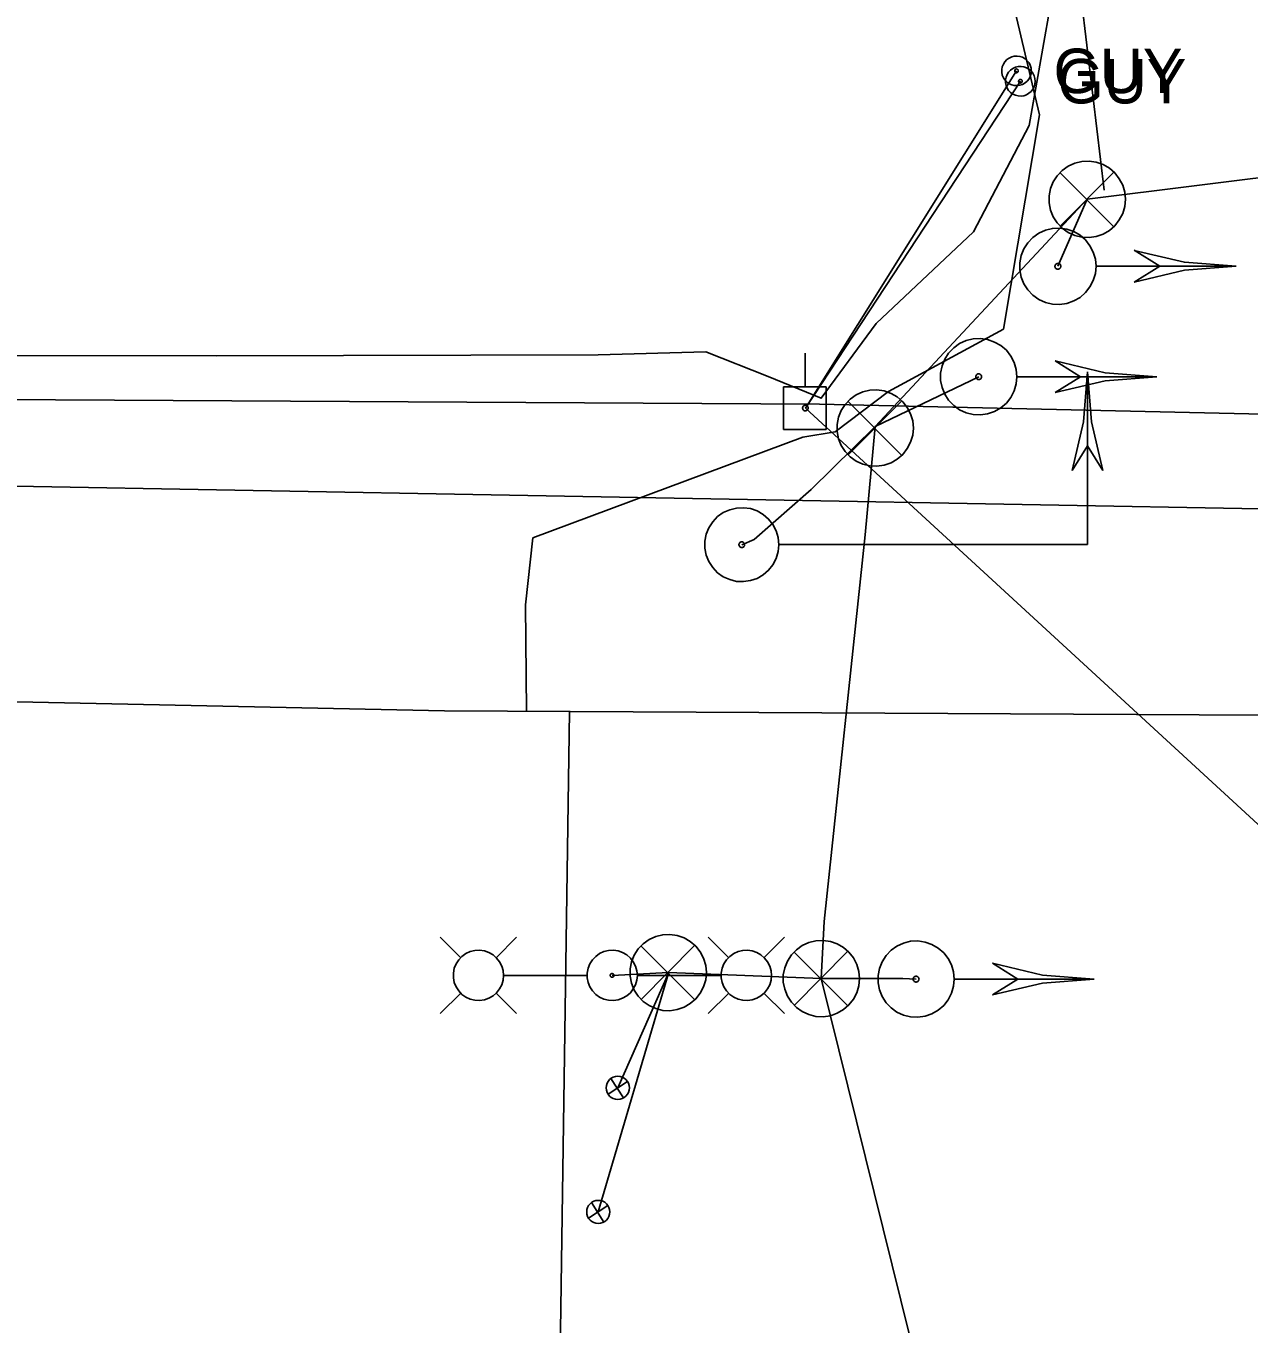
# Model space of a CAD drawing. Extents: x 596028 to 606371, y 330010 to 403088.
# Drawn here: x 604901.1 to 605006.9, y 349899.9 to 350012.1 of the extents above; entities that cross this region are included whole.
import ezdxf

# ---------------------------------------------------------------- set-up
doc = ezdxf.new("R2010")
doc.units = 0
for name, color, linetype in [('E_LTG', 7, 'Continuous'), ('E_LTG_CID', 7, 'Continuous'), ('E_SIG', 7, 'Continuous'), ('E_SIG_Conduit', 7, 'Continuous'), ('E_UTL_EGuyWire', 7, 'Continuous'), ('E_UTL_EPowerPole', 7, 'Continuous'), ('E_UTL_G_UG', 7, 'Continuous'), ('E_UTL_Loop_UG', 7, 'Continuous'), ('E_UTL_Overhead', 7, 'Continuous'), ('E_UTL_SAN_UG', 7, 'Continuous'), ('E_UTL_TV_UG', 7, 'Continuous')]:
    doc.layers.add(name, color=color, linetype=linetype)

# ---------------------------------------------------------------- blocks, each defined once
blk = doc.blocks.new('_U360')
at = {"layer": 'E_SIG'}
for p, q in [((-6.09, 0.4), (6.1, 0.4)), ((0, 6.1), (0, -6.1))]:
    blk.add_line(p, q, dxfattribs=at)
blk.add_circle((0, 0.01), 6.1, dxfattribs=at)
blk = doc.blocks.new('_U361')
at = {"layer": 'E_SIG'}
for p, q in [((-6.09, 0.4), (6.1, 0.4)), ((0, 6.1), (0, -6.1))]:
    blk.add_line(p, q, dxfattribs=at)
blk.add_circle((0, 0.01), 6.1, dxfattribs=at)

msp = doc.modelspace()

# ---------------------------------------------------------------- linework, layer by layer
at = {"layer": 'E_LTG'}
for points in [[(604938.74, 349931.53), (604936.97, 349933.3)], [(604941.79, 349931.53), (604943.57, 349933.3)], [(604961.92, 349931.53), (604960.14, 349933.3)], [(604964.96, 349931.53), (604966.74, 349933.3)], [(604942.44, 349930), (604942.4, 349930.42), (604942.29, 349930.81), (604942.1, 349931.18), (604941.84, 349931.5), (604941.53, 349931.78), (604941.17, 349931.98), (604940.78, 349932.12), (604940.37, 349932.18), (604939.96, 349932.16), (604939.56, 349932.06), (604939.18, 349931.89), (604938.84, 349931.65), (604938.56, 349931.35), (604938.33, 349931), (604938.18, 349930.62), (604938.1, 349930.21), (604938.1, 349929.8), (604938.18, 349929.39), (604938.33, 349929.01), (604938.56, 349928.66), (604938.84, 349928.36), (604939.18, 349928.12), (604939.56, 349927.95), (604939.96, 349927.85), (604940.37, 349927.83), (604940.78, 349927.89), (604941.17, 349928.02), (604941.53, 349928.23), (604941.84, 349928.5), (604942.1, 349928.83), (604942.29, 349929.19), (604942.4, 349929.59), (604942.44, 349930)], [(604954.01, 349930), (604953.97, 349930.41), (604953.85, 349930.81), (604953.66, 349931.18), (604953.41, 349931.5), (604953.1, 349931.78), (604952.74, 349931.98), (604952.35, 349932.12), (604951.94, 349932.18), (604951.52, 349932.16), (604951.12, 349932.06), (604950.75, 349931.89), (604950.41, 349931.65), (604950.12, 349931.35), (604949.9, 349931), (604949.75, 349930.62), (604949.67, 349930.21), (604949.67, 349929.8), (604949.75, 349929.39), (604949.9, 349929.01), (604950.12, 349928.66), (604950.41, 349928.36), (604950.75, 349928.12), (604951.12, 349927.95), (604951.52, 349927.85), (604951.94, 349927.83), (604952.35, 349927.89), (604952.74, 349928.02), (604953.1, 349928.23), (604953.41, 349928.5), (604953.66, 349928.83), (604953.85, 349929.19), (604953.97, 349929.59), (604954.01, 349930)], [(604965.61, 349930), (604965.57, 349930.41), (604965.46, 349930.81), (604965.27, 349931.18), (604965.01, 349931.5), (604964.7, 349931.78), (604964.34, 349931.98), (604963.95, 349932.12), (604963.54, 349932.18), (604963.13, 349932.16), (604962.73, 349932.06), (604962.35, 349931.89), (604962.01, 349931.65), (604961.73, 349931.35), (604961.5, 349931), (604961.35, 349930.62), (604961.27, 349930.21), (604961.27, 349929.8), (604961.35, 349929.39), (604961.5, 349929.01), (604961.73, 349928.66), (604962.01, 349928.36), (604962.35, 349928.12), (604962.73, 349927.95), (604963.13, 349927.85), (604963.54, 349927.83), (604963.95, 349927.89), (604964.34, 349928.02), (604964.7, 349928.23), (604965.01, 349928.5), (604965.27, 349928.83), (604965.46, 349929.19), (604965.57, 349929.59), (604965.61, 349930)], [(604942.48, 349930), (604949.66, 349930)], [(604952, 349930), (604952, 349930.03), (604951.99, 349930.06), (604951.97, 349930.09), (604951.95, 349930.12), (604951.93, 349930.14), (604951.9, 349930.15), (604951.87, 349930.16), (604951.84, 349930.17), (604951.81, 349930.17), (604951.78, 349930.16), (604951.75, 349930.15), (604951.73, 349930.13), (604951.7, 349930.11), (604951.69, 349930.08), (604951.67, 349930.05), (604951.67, 349930.02), (604951.67, 349929.99), (604951.67, 349929.96), (604951.69, 349929.93), (604951.7, 349929.9), (604951.73, 349929.88), (604951.75, 349929.86), (604951.78, 349929.85), (604951.81, 349929.84), (604951.84, 349929.84), (604951.87, 349929.84), (604951.9, 349929.85), (604951.93, 349929.87), (604951.95, 349929.89), (604951.97, 349929.91), (604951.99, 349929.94), (604952, 349929.97), (604952, 349930)], [(604961.22, 349930), (604954.05, 349930)], [(604938.74, 349928.48), (604936.97, 349926.7)], [(604941.79, 349928.48), (604943.57, 349926.7)], [(604961.92, 349928.48), (604960.14, 349926.7)], [(604964.96, 349928.48), (604966.74, 349926.7)]]:
    msp.add_lwpolyline(points, dxfattribs=at)
at = {"layer": 'E_LTG_CID'}
msp.add_lwpolyline([(604956.7, 349930.25), (604951.83, 349930)], dxfattribs=at)
at = {"layer": 'E_SIG'}
for points in [[(604996.22, 349997.12), (604996.16, 349997.74), (604995.98, 349998.35), (604995.69, 349998.9), (604995.31, 349999.4), (604994.83, 349999.81), (604994.29, 350000.12), (604993.7, 350000.33), (604993.08, 350000.42), (604992.45, 350000.39), (604991.84, 350000.24), (604991.27, 349999.98), (604990.76, 349999.61), (604990.32, 349999.16), (604989.98, 349998.63), (604989.75, 349998.05), (604989.63, 349997.43), (604989.63, 349996.81), (604989.75, 349996.19), (604989.98, 349995.61), (604990.32, 349995.08), (604990.76, 349994.63), (604991.27, 349994.26), (604991.84, 349994), (604992.45, 349993.85), (604993.08, 349993.82), (604993.7, 349993.91), (604994.29, 349994.12), (604994.83, 349994.43), (604995.31, 349994.84), (604995.69, 349995.34), (604995.98, 349995.89), (604996.16, 349996.5), (604996.22, 349997.12)], [(604995.18, 349999.45), (604990.57, 349994.8)], [(604990.57, 349999.41), (604995.22, 349994.75)], [(604993.68, 349991.33), (604993.62, 349991.95), (604993.44, 349992.56), (604993.15, 349993.11), (604992.76, 349993.61), (604992.29, 349994.02), (604991.75, 349994.33), (604991.15, 349994.54), (604990.53, 349994.63), (604989.91, 349994.6), (604989.3, 349994.45), (604988.73, 349994.19), (604988.21, 349993.82), (604987.78, 349993.37), (604987.44, 349992.84), (604987.21, 349992.26), (604987.09, 349991.64), (604987.09, 349991.02), (604987.21, 349990.4), (604987.44, 349989.82), (604987.78, 349989.29), (604988.21, 349988.84), (604988.73, 349988.47), (604989.3, 349988.21), (604989.91, 349988.06), (604990.53, 349988.03), (604991.15, 349988.12), (604991.75, 349988.33), (604992.29, 349988.64), (604992.76, 349989.05), (604993.15, 349989.55), (604993.44, 349990.1), (604993.62, 349990.7), (604993.68, 349991.33)], [(604999.18, 349991.33), (604996.98, 349992.71)], [(605005.78, 349991.33), (605001.32, 349991.68), (604996.98, 349992.7)], [(604990.63, 349991.33), (604990.62, 349991.38), (604990.61, 349991.42), (604990.59, 349991.47), (604990.56, 349991.5), (604990.52, 349991.54), (604990.48, 349991.56), (604990.44, 349991.57), (604990.39, 349991.58), (604990.34, 349991.58), (604990.29, 349991.57), (604990.25, 349991.55), (604990.21, 349991.52), (604990.18, 349991.49), (604990.15, 349991.45), (604990.13, 349991.4), (604990.12, 349991.35), (604990.12, 349991.31), (604990.13, 349991.26), (604990.15, 349991.21), (604990.18, 349991.17), (604990.21, 349991.14), (604990.25, 349991.11), (604990.29, 349991.09), (604990.34, 349991.08), (604990.39, 349991.08), (604990.44, 349991.08), (604990.48, 349991.1), (604990.52, 349991.12), (604990.56, 349991.16), (604990.59, 349991.19), (604990.61, 349991.24), (604990.62, 349991.28), (604990.63, 349991.33)], [(605005.78, 349991.33), (604993.73, 349991.33)], [(605005.78, 349991.33), (605001.32, 349990.98), (604996.98, 349989.95)], [(604996.98, 349989.96), (604999.18, 349991.33)], [(604986.83, 349981.78), (604986.77, 349982.4), (604986.59, 349983.01), (604986.3, 349983.56), (604985.92, 349984.06), (604985.44, 349984.47), (604984.9, 349984.78), (604984.3, 349984.99), (604983.68, 349985.07), (604983.06, 349985.04), (604982.45, 349984.9), (604981.88, 349984.64), (604981.37, 349984.27), (604980.93, 349983.82), (604980.59, 349983.29), (604980.36, 349982.71), (604980.24, 349982.09), (604980.24, 349981.46), (604980.36, 349980.85), (604980.59, 349980.27), (604980.93, 349979.74), (604981.37, 349979.28), (604981.88, 349978.92), (604982.45, 349978.66), (604983.06, 349978.51), (604983.68, 349978.48), (604984.3, 349978.57), (604984.9, 349978.78), (604985.44, 349979.09), (604985.92, 349979.5), (604986.3, 349979.99), (604986.59, 349980.55), (604986.77, 349981.15), (604986.83, 349981.78)], [(604998.93, 349981.78), (604994.47, 349982.12), (604990.13, 349983.15)], [(604992.33, 349981.78), (604990.13, 349983.15)], [(604983.78, 349981.78), (604983.77, 349981.83), (604983.76, 349981.87), (604983.74, 349981.91), (604983.71, 349981.95), (604983.67, 349981.98), (604983.63, 349982.01), (604983.59, 349982.02), (604983.54, 349982.03), (604983.49, 349982.03), (604983.44, 349982.02), (604983.4, 349982), (604983.36, 349981.97), (604983.33, 349981.93), (604983.3, 349981.89), (604983.28, 349981.85), (604983.28, 349981.8), (604983.28, 349981.75), (604983.28, 349981.71), (604983.3, 349981.66), (604983.33, 349981.62), (604983.36, 349981.59), (604983.4, 349981.56), (604983.44, 349981.54), (604983.49, 349981.53), (604983.54, 349981.53), (604983.59, 349981.53), (604983.63, 349981.55), (604983.67, 349981.57), (604983.71, 349981.6), (604983.74, 349981.64), (604983.76, 349981.68), (604983.77, 349981.73), (604983.78, 349981.78)], [(604998.93, 349981.78), (604986.88, 349981.78)], [(604998.93, 349981.78), (604994.47, 349981.43), (604990.13, 349980.4)], [(604990.13, 349980.41), (604992.33, 349981.78)], [(604992.94, 349982.2), (604992.6, 349977.88), (604991.6, 349973.66)], [(604992.94, 349967.26), (604992.94, 349982.2)], [(604992.94, 349982.2), (604993.27, 349977.88), (604994.27, 349973.66)], [(604977.88, 349977.34), (604977.82, 349977.96), (604977.64, 349978.57), (604977.35, 349979.12), (604976.96, 349979.62), (604976.49, 349980.03), (604975.95, 349980.34), (604975.35, 349980.55), (604974.73, 349980.64), (604974.11, 349980.61), (604973.5, 349980.46), (604972.93, 349980.2), (604972.42, 349979.83), (604971.98, 349979.38), (604971.64, 349978.85), (604971.41, 349978.27), (604971.29, 349977.65), (604971.29, 349977.03), (604971.41, 349976.41), (604971.64, 349975.83), (604971.98, 349975.3), (604972.42, 349974.85), (604972.93, 349974.48), (604973.5, 349974.22), (604974.11, 349974.07), (604974.73, 349974.04), (604975.35, 349974.13), (604975.95, 349974.34), (604976.49, 349974.65), (604976.96, 349975.06), (604977.35, 349975.56), (604977.64, 349976.11), (604977.82, 349976.72), (604977.88, 349977.34)], [(604976.84, 349979.67), (604972.23, 349975.02)], [(604972.23, 349979.63), (604976.88, 349974.97)], [(604992.94, 349975.8), (604991.6, 349973.66)], [(604994.27, 349973.66), (604992.94, 349975.8)], [(604966.25, 349967.25), (604966.19, 349967.86), (604966.02, 349968.44), (604965.74, 349968.99), (604965.36, 349969.46), (604964.9, 349969.86), (604964.37, 349970.17), (604963.8, 349970.37), (604963.2, 349970.45), (604962.59, 349970.42), (604962, 349970.28), (604961.44, 349970.03), (604960.95, 349969.68), (604960.53, 349969.23), (604960.2, 349968.72), (604959.97, 349968.16), (604959.86, 349967.56), (604959.86, 349966.95), (604959.97, 349966.35), (604960.2, 349965.79), (604960.53, 349965.27), (604960.95, 349964.83), (604961.44, 349964.48), (604962, 349964.23), (604962.59, 349964.08), (604963.2, 349964.06), (604963.8, 349964.14), (604964.37, 349964.34), (604964.9, 349964.65), (604965.36, 349965.04), (604965.74, 349965.52), (604966.02, 349966.06), (604966.19, 349966.65), (604966.25, 349967.25)], [(604963.29, 349967.25), (604963.28, 349967.3), (604963.27, 349967.35), (604963.25, 349967.39), (604963.22, 349967.42), (604963.19, 349967.45), (604963.15, 349967.48), (604963.1, 349967.49), (604963.06, 349967.5), (604963.01, 349967.5), (604962.96, 349967.49), (604962.92, 349967.47), (604962.88, 349967.44), (604962.85, 349967.41), (604962.83, 349967.37), (604962.81, 349967.32), (604962.8, 349967.28), (604962.8, 349967.23), (604962.81, 349967.19), (604962.83, 349967.14), (604962.85, 349967.1), (604962.88, 349967.07), (604962.92, 349967.04), (604962.96, 349967.02), (604963.01, 349967.01), (604963.06, 349967.01), (604963.1, 349967.02), (604963.15, 349967.03), (604963.19, 349967.05), (604963.22, 349967.09), (604963.25, 349967.12), (604963.27, 349967.16), (604963.28, 349967.21), (604963.29, 349967.25)], [(604992.94, 349967.26), (604966.3, 349967.26)], [(604985.46, 349967.26), (604985.46, 349967.26)], [(604959.98, 349930.25), (604959.92, 349930.87), (604959.74, 349931.48), (604959.45, 349932.03), (604959.07, 349932.53), (604958.59, 349932.94), (604958.05, 349933.25), (604957.46, 349933.46), (604956.83, 349933.55), (604956.21, 349933.52), (604955.6, 349933.37), (604955.03, 349933.11), (604954.52, 349932.74), (604954.08, 349932.29), (604953.74, 349931.76), (604953.51, 349931.18), (604953.39, 349930.56), (604953.39, 349929.94), (604953.51, 349929.32), (604953.74, 349928.74), (604954.08, 349928.21), (604954.52, 349927.75), (604955.03, 349927.39), (604955.6, 349927.13), (604956.21, 349926.98), (604956.83, 349926.95), (604957.46, 349927.04), (604958.05, 349927.25), (604958.59, 349927.56), (604959.07, 349927.97), (604959.45, 349928.46), (604959.74, 349929.02), (604959.92, 349929.62), (604959.98, 349930.25)], [(604958.94, 349932.58), (604954.33, 349927.93)], [(604954.33, 349932.54), (604958.98, 349927.88)], [(604973.22, 349929.73), (604973.16, 349930.35), (604972.98, 349930.95), (604972.7, 349931.51), (604972.31, 349932.01), (604971.83, 349932.42), (604971.29, 349932.73), (604970.7, 349932.94), (604970.08, 349933.02), (604969.45, 349932.99), (604968.84, 349932.85), (604968.27, 349932.59), (604967.76, 349932.22), (604967.33, 349931.77), (604966.99, 349931.24), (604966.75, 349930.66), (604966.63, 349930.04), (604966.63, 349929.41), (604966.75, 349928.8), (604966.99, 349928.22), (604967.33, 349927.69), (604967.76, 349927.23), (604968.27, 349926.87), (604968.84, 349926.61), (604969.45, 349926.46), (604970.08, 349926.43), (604970.7, 349926.52), (604971.29, 349926.73), (604971.83, 349927.04), (604972.31, 349927.45), (604972.7, 349927.94), (604972.98, 349928.5), (604973.16, 349929.1), (604973.22, 349929.73)], [(604981.41, 349929.68), (604981.35, 349930.31), (604981.18, 349930.91), (604980.89, 349931.47), (604980.5, 349931.96), (604980.03, 349932.37), (604979.48, 349932.68), (604978.89, 349932.89), (604978.27, 349932.98), (604977.64, 349932.95), (604977.03, 349932.8), (604976.46, 349932.54), (604975.95, 349932.18), (604975.52, 349931.72), (604975.18, 349931.19), (604974.95, 349930.61), (604974.83, 349930), (604974.83, 349929.37), (604974.95, 349928.75), (604975.18, 349928.17), (604975.52, 349927.64), (604975.95, 349927.19), (604976.46, 349926.82), (604977.03, 349926.56), (604977.64, 349926.42), (604978.27, 349926.39), (604978.89, 349926.48), (604979.48, 349926.68), (604980.03, 349926.99), (604980.5, 349927.41), (604980.89, 349927.9), (604981.18, 349928.46), (604981.35, 349929.06), (604981.41, 349929.68)], [(604972.18, 349932.06), (604967.57, 349927.41)], [(604967.57, 349932.02), (604972.22, 349927.36)], [(604993.51, 349929.68), (604989.06, 349930.03), (604984.71, 349931.06)], [(604986.91, 349929.68), (604984.71, 349931.06)], [(604978.37, 349929.68), (604978.36, 349929.73), (604978.35, 349929.78), (604978.33, 349929.82), (604978.3, 349929.86), (604978.26, 349929.89), (604978.22, 349929.91), (604978.17, 349929.93), (604978.13, 349929.93), (604978.08, 349929.93), (604978.03, 349929.92), (604977.99, 349929.9), (604977.95, 349929.87), (604977.92, 349929.84), (604977.89, 349929.8), (604977.87, 349929.75), (604977.86, 349929.71), (604977.86, 349929.66), (604977.87, 349929.61), (604977.89, 349929.57), (604977.92, 349929.53), (604977.95, 349929.49), (604977.99, 349929.46), (604978.03, 349929.44), (604978.08, 349929.43), (604978.13, 349929.43), (604978.17, 349929.44), (604978.22, 349929.45), (604978.26, 349929.48), (604978.3, 349929.51), (604978.33, 349929.55), (604978.35, 349929.59), (604978.36, 349929.63), (604978.37, 349929.68)], [(604993.51, 349929.68), (604981.47, 349929.68)], [(604993.51, 349929.68), (604989.06, 349929.34), (604984.71, 349928.31)], [(604984.71, 349928.31), (604986.91, 349929.68)]]:
    msp.add_lwpolyline(points, dxfattribs=at)
at = {"layer": 'E_SIG_Conduit'}
for points in [[(604994.39, 349997.92), (604992.49, 350013.82), (604988.54, 350029.6)], [(604992.92, 349997.12), (605041.26, 350003.17), (605045.68, 350004), (605067.59, 350003.14), (605103.15, 349993.06), (605106.99, 349992.73)], [(604963.04, 349967.25), (604964.1, 349967.7), (604969.04, 349972.01), (604974.59, 349977.47), (604992.92, 349997.12)], [(604992.92, 349997.12), (604990.38, 349991.33)], [(604974.59, 349977.47), (604983.53, 349981.78)], [(604974.59, 349977.47), (604973.7, 349968.11), (604970.17, 349934.65), (604969.92, 349929.73)], [(604969.92, 349929.73), (604956.7, 349930.25)], [(604969.92, 349929.73), (604985.98, 349864.78), (604987.57, 349858.81)], [(604969.92, 349929.73), (604976.98, 349929.73), (604978.11, 349929.68)]]:
    msp.add_lwpolyline(points, dxfattribs=at)
at = {"layer": 'E_UTL_EGuyWire'}
for p in [(604986.8, 350008.23), (604987.13, 350007.33)]:
    msp.add_line(p, (604968.54, 349979.07), dxfattribs=at)
for points in [[(604988.08, 350008.23), (604988.06, 350008.47), (604987.99, 350008.71), (604987.88, 350008.92), (604987.72, 350009.11), (604987.54, 350009.27), (604987.33, 350009.4), (604987.1, 350009.48), (604986.86, 350009.51), (604986.61, 350009.5), (604986.38, 350009.44), (604986.15, 350009.34), (604985.96, 350009.2), (604985.79, 350009.02), (604985.66, 350008.82), (604985.56, 350008.59), (604985.52, 350008.35), (604985.52, 350008.11), (604985.56, 350007.87), (604985.66, 350007.64), (604985.79, 350007.44), (604985.96, 350007.26), (604986.15, 350007.12), (604986.38, 350007.02), (604986.61, 350006.96), (604986.86, 350006.95), (604987.1, 350006.98), (604987.33, 350007.06), (604987.54, 350007.18), (604987.72, 350007.34), (604987.88, 350007.54), (604987.99, 350007.75), (604988.06, 350007.99), (604988.08, 350008.23)], [(604988.41, 350007.33), (604988.39, 350007.57), (604988.32, 350007.81), (604988.21, 350008.02), (604988.06, 350008.22), (604987.87, 350008.38), (604987.66, 350008.5), (604987.43, 350008.58), (604987.19, 350008.61), (604986.95, 350008.6), (604986.71, 350008.54), (604986.49, 350008.44), (604986.29, 350008.3), (604986.12, 350008.12), (604985.99, 350007.92), (604985.9, 350007.69), (604985.85, 350007.45), (604985.85, 350007.21), (604985.9, 350006.97), (604985.99, 350006.74), (604986.12, 350006.54), (604986.29, 350006.36), (604986.49, 350006.22), (604986.71, 350006.12), (604986.95, 350006.06), (604987.19, 350006.05), (604987.43, 350006.08), (604987.66, 350006.16), (604987.87, 350006.29), (604988.06, 350006.45), (604988.21, 350006.64), (604988.32, 350006.85), (604988.39, 350007.09), (604988.41, 350007.33)], [(604986.96, 350008.23), (604986.95, 350008.26), (604986.94, 350008.29), (604986.93, 350008.32), (604986.91, 350008.34), (604986.89, 350008.36), (604986.86, 350008.37), (604986.83, 350008.38), (604986.8, 350008.39), (604986.77, 350008.39), (604986.74, 350008.38), (604986.72, 350008.37), (604986.69, 350008.35), (604986.67, 350008.33), (604986.65, 350008.3), (604986.64, 350008.27), (604986.64, 350008.24), (604986.64, 350008.21), (604986.64, 350008.18), (604986.65, 350008.16), (604986.67, 350008.13), (604986.69, 350008.11), (604986.72, 350008.09), (604986.74, 350008.08), (604986.77, 350008.07), (604986.8, 350008.07), (604986.83, 350008.07), (604986.86, 350008.08), (604986.89, 350008.1), (604986.91, 350008.12), (604986.93, 350008.14), (604986.94, 350008.17), (604986.95, 350008.2), (604986.96, 350008.23)], [(604987.29, 350007.33), (604987.29, 350007.36), (604987.28, 350007.39), (604987.26, 350007.42), (604987.25, 350007.44), (604987.22, 350007.46), (604987.2, 350007.48), (604987.17, 350007.49), (604987.14, 350007.49), (604987.11, 350007.49), (604987.08, 350007.48), (604987.05, 350007.47), (604987.02, 350007.45), (604987, 350007.43), (604986.99, 350007.4), (604986.98, 350007.38), (604986.97, 350007.35), (604986.97, 350007.32), (604986.98, 350007.29), (604986.99, 350007.26), (604987, 350007.23), (604987.02, 350007.21), (604987.05, 350007.19), (604987.08, 350007.18), (604987.11, 350007.17), (604987.14, 350007.17), (604987.17, 350007.18), (604987.2, 350007.19), (604987.22, 350007.2), (604987.25, 350007.22), (604987.26, 350007.24), (604987.28, 350007.27), (604987.29, 350007.3), (604987.29, 350007.33)]]:
    msp.add_lwpolyline(points, dxfattribs=at)
at = {"layer": 'E_UTL_EPowerPole'}
for points in [[(604968.51, 349980.91), (604968.51, 349983.82)], [(604970.35, 349980.91), (604966.66, 349980.91)], [(604966.66, 349980.91), (604966.66, 349977.22)], [(604970.35, 349977.22), (604970.35, 349980.91)], [(604968.78, 349979.07), (604968.77, 349979.12), (604968.76, 349979.16), (604968.74, 349979.2), (604968.71, 349979.23), (604968.68, 349979.26), (604968.64, 349979.29), (604968.6, 349979.3), (604968.55, 349979.31), (604968.51, 349979.31), (604968.46, 349979.3), (604968.42, 349979.28), (604968.38, 349979.25), (604968.35, 349979.22), (604968.33, 349979.18), (604968.31, 349979.14), (604968.3, 349979.09), (604968.3, 349979.05), (604968.31, 349979), (604968.33, 349978.96), (604968.35, 349978.92), (604968.38, 349978.89), (604968.42, 349978.86), (604968.46, 349978.84), (604968.51, 349978.83), (604968.55, 349978.83), (604968.6, 349978.84), (604968.64, 349978.85), (604968.68, 349978.88), (604968.71, 349978.91), (604968.74, 349978.94), (604968.76, 349978.98), (604968.77, 349979.02), (604968.78, 349979.07)], [(604966.66, 349977.22), (604970.35, 349977.22)]]:
    msp.add_lwpolyline(points, dxfattribs=at)
at = {"layer": 'E_UTL_G_UG'}
msp.add_line((604946.54, 349844.45), (604948.15, 349952.82), dxfattribs=at)
for points in [[(604944.96, 349967.84), (604968.33, 349976.55), (604971.11, 349977.02), (604975.73, 349980.5), (604985.67, 349985.89), (604988.78, 350004.44), (604973.16, 350070.59)], [(604944.41, 349952.84), (604944.33, 349962.04), (604944.96, 349967.84)], [(604797.56, 349955.68), (604807.59, 349955.39), (604836.44, 349954.33), (604859.25, 349954.54), (604937.34, 349952.88), (605008.04, 349952.52)]]:
    msp.add_lwpolyline(points, dxfattribs=at)
at = {"layer": 'E_UTL_Loop_UG'}
for p in [(604950.63, 349909.55), (604952.32, 349920.28)]:
    msp.add_line(p, (604956.69, 349930.2), dxfattribs=at)
at = {"layer": 'E_UTL_Overhead'}
msp.add_line((604968.54, 349979.07), (605141.52, 349819.92), dxfattribs=at)
msp.add_lwpolyline([(603181.28, 350035.1), (603329.32, 350032.13), (603487.19, 350051.84), (603697.5, 350053.11), (603794.73, 350045.64), (603986.8, 350030.72), (604135.55, 350019.1), (604355.8, 350001.36), (604456.04, 349993.24), (604557.11, 349986.14), (604654.49, 349982.64), (604747.33, 349981.14), (604855.96, 349980.06), (604969.76, 349979.4), (605156.33, 349975.18)], dxfattribs=at)
at = {"layer": 'E_UTL_SAN_UG'}
msp.add_line((604737.68, 349975.25), (605035.81, 349969.84), dxfattribs=at)
at = {"layer": 'E_UTL_TV_UG'}
msp.add_lwpolyline([(604988.28, 350041.13), (604990.53, 350027.64), (604989.92, 350014.96), (604987.9, 350003.51), (604983.08, 349994.32), (604974.67, 349986.39), (604969.91, 349979.91), (604965.32, 349981.81), (604959.93, 349983.92), (604950.62, 349983.67), (604917.59, 349983.57), (604891.81, 349983.61), (604881.88, 349980.97), (604863.41, 349979.68), (604856.96, 349980.07), (604850.48, 349979.85), (604818.52, 349980.13), (604815.19, 349979.98), (604813.09, 349978.71), (604812.75, 349974.57), (604812.97, 349964.56), (604812.11, 349933.63), (604812.58, 349907.79), (604810.24, 349875.64)], dxfattribs=at)

# ---------------------------------------------------------------- block references
at = {"layer": 'E_SIG_Conduit', "xscale": 0.16404166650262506, "yscale": 0.16404166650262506, "rotation": 122.69997330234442}
for name, p in [('_U361', (604952.32, 349920.28)), ('_U360', (604950.63, 349909.55))]:
    msp.add_blockref(name, p, dxfattribs=at)

# ---------------------------------------------------------------- texts
at = {"layer": 'E_UTL_EGuyWire'}
for p in [(604990, 350006.3), (604990.34, 350005.41)]:
    msp.add_text('GUY', height=3.85, dxfattribs=at).set_placement(p)

doc.saveas('drawing.dxf')
